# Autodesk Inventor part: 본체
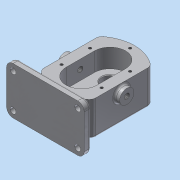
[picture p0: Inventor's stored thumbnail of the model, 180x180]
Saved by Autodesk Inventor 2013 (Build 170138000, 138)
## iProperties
Created: 2019-03
Part Number: 본체
Material: 알루미늄 6061
Document SubType Name: Modeling
Designer: dgall
Density: 2.71 g/cm^3
Mass: 1191.56 g
Surface Area: 719.273 cm^2
Volume: 439.69 cm^3
Author: dgall
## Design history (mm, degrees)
sketch "스케치1"
  geometry: L1 (-40, -15.279)-(-40, -104.721); L2 (40, -15.279)-(40, -104.721); A1 r 60 centre (0, -60) between (40, -15.279) and (-40, -15.279); A2 r 60 centre (0, -60) between (-40, -104.721) and (40, -104.721); 1 further point
  constraints: 6 point on circle, 4 end point, 2 centre point, 1 coincident, 1 concentric, 1 parallel, 1 vertical, 1 vertical alignment
  dimensions: "d5" = 60 radius of A1; "d7" = 80 distance between parallel lines of L2 L1
extrude "돌출1" new body sketch "스케치1" stored distance "d8" = 53; taper "d9" = 0 deg
sketch "스케치2"
  geometry: L1 (40, -104.721)-(40, -15.279) reference; L2 (-24, -38)-(-24, -82); L3 (24, -38)-(24, -82); A1 r 60 centre (0, -60) between (40, -15.279) and (-40, -15.279) reference; A2 r 24 centre (0, -38) between (24, -38) and (-24, -38); A3 r 24 centre (0, -82) between (-24, -82) and (24, -82); 1 further point
  constraints: 4 end point, 4 point on circle, 3 vertical alignment, 2 centre point, 2 tangent, 1 equal radius, 1 parallel, 1 vertical
  dimensions: "d10" = 24 radius of A2; "d12" = 22 distance of A2.centre A1.centre; "d13" = 22 distance of A3.centre A1.centre
extrude "돌출2" cut sketch "스케치2" distance "d14" = 29; taper "d15" = 0 deg
sketch "스케치3"
  geometry: C1 r 19 at (0, -38); A1 r 60 centre (0, -60) between (40, -15.279) and (-40, -15.279) reference; 1 further point
  constraints: 1 centre point, 1 vertical alignment
  dimensions: "d16" = 38 diameter of C1; "d17" = 22 distance of A1.centre C1.centre
extrude "돌출3" join sketch "스케치3" distance "d18" = 17; taper "d19" = 0 deg
sketch "스케치4"
  geometry: L1 (-14, -2.5)-(-14, 26.5) reference; L2 (-14, 26.5)-(0, 26.5) reference; L3 (0, 26.5)-(0, -26.5) reference; L4 (0, -26.5)-(-19, -26.5) reference; L5 (-19, -26.5)-(-19, -43.5) reference; L6 (-19, -43.5)-(-57, -43.5) reference; L7 (-57, -43.5)-(-57, -26.5) reference; L8 (-57, -26.5)-(-120, -26.5) reference; L9 (-120, -26.5)-(-120, 26.5) reference; L10 (-120, 26.5)-(-106, 26.5) reference; L11 (-106, 26.5)-(-106, -2.5) reference; L12 (-106, -2.5)-(-14, -2.5) reference; L13 (-38, -2.5)-(-14, -2.5) reference; L14 (-38, -2.5)-(-38, -43.5); L15 (-25.5, -2.5)-(-25.5, -17.5); L16 (-25.5, -17.5)-(-29.5, -17.5); L17 (-29.5, -17.5)-(-29.5, -36.2); L18 (-29.5, -36.2)-(-24, -36.2); L19 (-24, -36.2)-(-24, -43.5); 1 further point
  constraints: 12 end point, 4 perpendicular, 3 point on line, 2 parallel, 1 midpoint
  dimensions: "d20" = 19 distance from line of L14.end L5; "d22" = 25 diameter of L15 L14; "d23" = 17 diameter of L17 L14; "d24" = 28 diameter of L19 L14; "d25" = 15 distance of L15.start L15.end; "d26" = 7.3 distance of L18.end L19.end
revolve "회전1" sketch "스케치4" stored, may be unused: angle "d27" = 90 deg
sketch "스케치5"
  geometry: C1 r 12.5 at (0, -82); A1 r 24 centre (0, -82) between (-24, -82) and (24, -82) reference; 1 further point
  constraints: 1 centre point, 1 coincident
  dimensions: "d30" = 25 diameter of C1
extrude "돌출4" cut sketch "스케치5" distance "d32" = 15; taper "d33" = 0 deg
sketch "스케치6"
  geometry: L1 (0, 0)-(0, 89.443) reference; L2 (70, 47.721)-(70, 85.721) reference; L3 (70, 66.721)-(0, 66.721); L4 (0, 66.721)-(29, 66.721) reference; C1 r 11 at (14, 44.721); 1 further point
  constraints: 2 end point, 1 centre point, 1 collinear, 1 midpoint
  dimensions: "d34" = 22 diameter of C1; "d36" = 14 distance from line of C1.centre L1; "d37" = 22 distance from line of C1.centre L3
extrude "돌출5" join sketch "스케치6" distance "d38" = 8; taper "d39" = 0 deg
node "작업 평면1"
hole "구멍1" diameter "d42" = 8.376; stored, may be unused: countersink angle "d46" = 90 deg, drill point angle "d48" = 118 deg; dims "d40" = 10, "d41" = 10, "d43" = 6, "d44" = 4, "d45" = 2, "d47" = 8
node "작업 평면2"
sketch "스케치7"
  geometry: L1 (60, 46.5)-(-60, 46.5); L2 (-60, 46.5)-(-60, -26.5); L3 (-60, -26.5)-(60, -26.5); L4 (60, -26.5)-(60, 46.5); L5 (-40, -26.5)-(40, -26.5) reference; 4 further points
  constraints: 8 end point, 3 midpoint, 2 parallel, 1 horizontal, 1 horizontal alignment, 1 perpendicular, 1 vertical alignment
  dimensions: "d50" = 73 distance of L3.end L1.start; "d52" = 120 distance of L1.start L1.end
extrude "돌출6" join sketch "스케치7" distance "d53" = 10; taper "d54" = 0 deg
fillet "모깎기1" dims "d55" = 10
sketch "스케치8"
  geometry: C1 r 4.5 at (-50, -36.5); A1 r 10 centre (-50, -36.5) between (-60, -36.5) and (-50, -46.5) reference; 1 further point
  constraints: 1 centre point, 1 coincident
  dimensions: "d56" = 9 diameter of C1
extrude "돌출7" cut sketch "스케치8" distance "d57" = 10; taper "d58" = 0 deg
sketch "스케치9"
  geometry: L1 (40, -104.721)-(40, -15.279) reference; L2 (-6, -119.699)-(-6, -128); L3 (6, -119.699)-(6, -128); L4 (-50, -128)-(50, -128) reference; C1 r 19 at (0, -38) reference; A1 r 60 centre (0, -60) between (-40, -104.721) and (40, -104.721) reference; A2 r 60 centre (0, -60) between (-40, -104.721) and (40, -104.721) reference; 1 further point
  constraints: 4 end point, 4 point on circle, 2 parallel, 2 point on line
  dimensions: "d65" = 6 distance from line of L2 C1.centre; "d66" = 12 distance between parallel lines of L3 L2
extrude "돌출8" join sketch "스케치9" distance "d67" = 43; taper "d68" = 0 deg
sketch "스케치10"
  geometry: A1 r 24 centre (0, -38) between (24, -38) and (-24, -38) reference; 2 further points
  constraints: 1 vertical alignment
  dimensions: "d69" = 31 distance of A1.centre point (0, -7)
hole "구멍2" sketch "스케치10" at (0, -7) diameter "d70" = 4.134; stored, may be unused: countersink angle "d74" = 90 deg, drill point angle "d76" = 118 deg; dims "d71" = 10, "d72" = 4, "d73" = 2, "d75" = 12
fillet "모깎기2" dims "d77" = 3
fillet "모깎기3" dims "d78" = 3
fillet "모깎기4" dims "d79" = 3
fillet "모깎기5" dims "d80" = 3
fillet "모깎기6" dims "d81" = 10
fillet "모깎기7" dims "d82" = 3
fillet "모깎기8" dims "d83" = 3
chamfer "모따기1" distance "d84" = 0.7; stored, may be unused: second distance "d85" = 2, angle "d86" = 30 deg
fillet "모깎기9" dims "d87" = 0.5
chamfer "모따기2" distance "d88" = 1; stored, may be unused: second distance "d89" = 2, angle "d90" = 30 deg
sketch "스케치11"
  geometry: C1 r 2.067 at (0, -7) reference; A1 r 24 centre (0, -82) between (-24, -82) and (24, -82) reference; 2 further points
  constraints: 1 vertical alignment
  dimensions: "d91" = 106 distance of point (0, -113) C1.centre
hole "구멍3" sketch "스케치11" at (0, -113) diameter "d92" = 4.134; stored, may be unused: countersink angle "d96" = 90 deg, drill point angle "d98" = 118 deg; dims "d93" = 10, "d94" = 4, "d95" = 2, "d97" = 12
sketch "스케치12"
  geometry: A1 r 60 centre (0, -60) between (36, -12) and (-36, -12) reference; A2 r 24 centre (0, -38) between (24, -38) and (-24, -38) reference; 5 further points
  constraints: 2 horizontal alignment, 2 vertical alignment
  dimensions: "d99" = 31 distance of point (-31, -38) A2.centre; "d100" = 31 distance of point (31, -38) A2.centre; "d101" = 22 vertical distance of A1.centre point (-31, -38); "d102" = 22 vertical distance of point (-31, -82) A1.centre
hole "구멍4" sketch "스케치12" at (-31, -38), (31, -38), (-31, -82), (31, -82) diameter "d103" = 4.134; stored, may be unused: countersink angle "d107" = 90 deg, drill point angle "d109" = 118 deg; dims "d104" = 10, "d105" = 4, "d106" = 2, "d108" = 12
sketch "스케치13"
  geometry: L1 (-50, -46.5)-(50, -46.5) reference; L2 (-60, 16.5)-(-60, -36.5) reference; 2 further points
  constraints: 1 other
  dimensions: "d110" = 10 distance from line of L1 point (0, -36.5); "d111" = 60 distance from line of point (0, -36.5) L2
feature "엠보싱1" sketch "스케치13" dims "d5" = 60, "d7" = 80, "d112" = 0.5, "d113" = 0
node "솔리드1"
mirror "대칭1"
mirror "대칭2"
pattern_linear "직사각형 패턴1" dims "d61" = 53
node "절단 모서리 투영1"
other parameters: "d49" = -138
